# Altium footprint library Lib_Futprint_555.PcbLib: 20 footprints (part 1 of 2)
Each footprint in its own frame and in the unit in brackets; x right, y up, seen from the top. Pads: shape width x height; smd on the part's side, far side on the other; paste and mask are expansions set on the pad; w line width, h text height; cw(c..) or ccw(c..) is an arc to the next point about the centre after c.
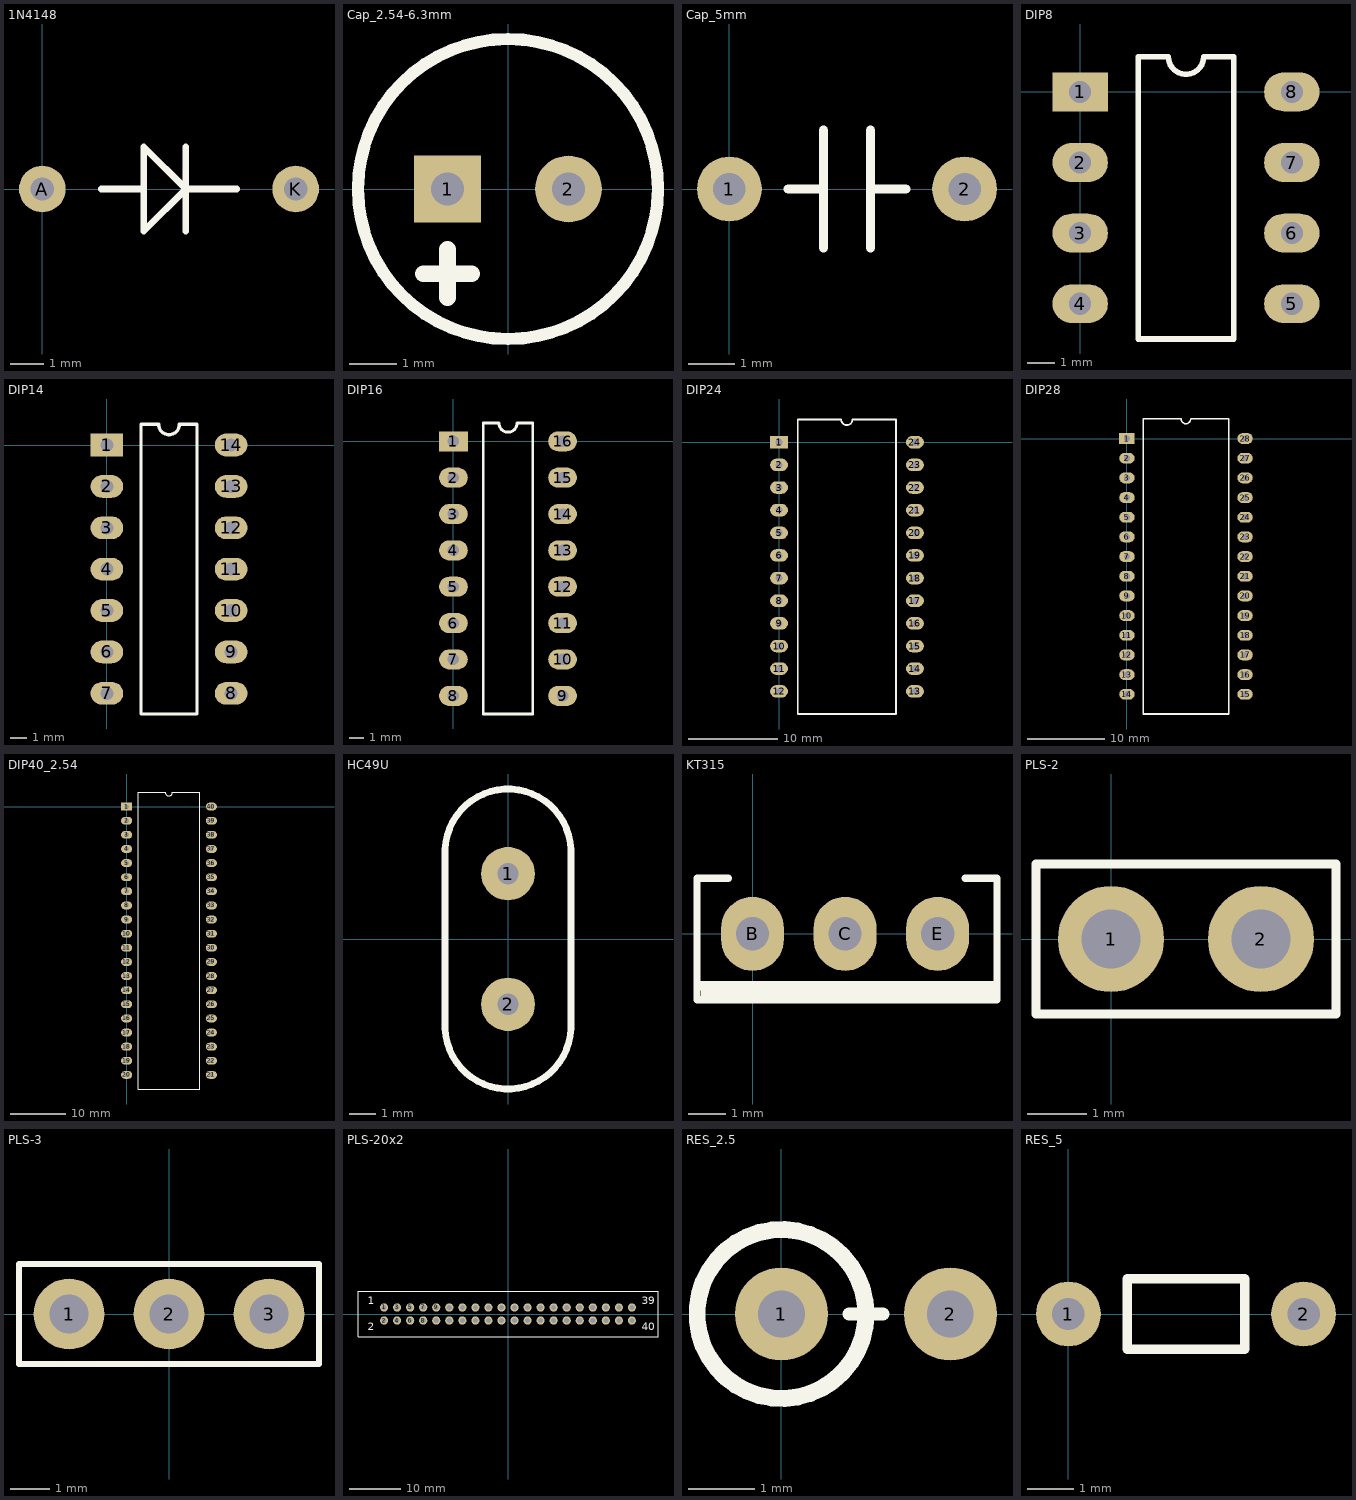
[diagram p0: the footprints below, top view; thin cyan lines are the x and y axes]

## 1N4148 [mm]
pads (2):
  round 1.4 hole 0.7: A(0,0) K(7.62,0)
Top Overlay:
  lines w0.2: 1.778,0 3.048,0 ; 4.318,-1.27 4.318,1.27 ; 5.842,0 4.318,0 ; 4.318,0 3.048,-1.27 3.048,1.27 4.318,0

## Cap_2.54-6.3mm [mm]
pads (2):
  rect 1.4x1.4 hole 0.7: 1(-1.27,0)
  round 1.4 hole 0.7: 2(1.27,0)
Top Overlay:
  circle w0.254: c0,0 r3.15
  lines w0.35: -1.778,-1.778 -0.762,-1.778 ; -1.27,-2.286 -1.27,-1.27
  text ".Designator" at 2.54,5.08 h1.52

## Cap_5mm [mm]
pads (2):
  round 1.4 hole 0.7: 1(0,0) 2(5.08,0)
Top Overlay:
  lines w0.2: 1.27,0 2.032,0 ; 2.032,-1.27 2.032,1.27 ; 3.048,-1.27 3.048,1.27 ; 3.048,0 3.81,0
  text ".Designator" at -0.254,2.032 h1.52

## DIP8 [mm]
pads (8):
  rect 2x1.4 hole 0.8: 1(0,0)
  oval 2x1.4 hole 0.8: 2(0,-2.54) 3(0,-5.08) 4(0,-7.62) 5(7.62,-7.62) 6(7.62,-5.08) 7(7.62,-2.54) 8(7.62,0)
Top Overlay:
  lines w0.2: 2.085,-8.89 5.535,-8.89 5.535,1.27 4.445,1.27 cw(c3.81,1.27) 3.175,1.27 2.085,1.27 2.085,-8.89
  text ".Designator" at 3.175,-0.635 h3.05

## DIP14 [mm]
pads (14):
  rect 2x1.4 hole 0.8: 1(0,0)
  oval 2x1.4 hole 0.8: 2(0,-2.54) 3(0,-5.08) 4(0,-7.62) 5(0,-10.16) 6(0,-12.7) 7(0,-15.24) 8(7.62,-15.24) 9(7.62,-12.7) 10(7.62,-10.16) 11(7.62,-7.62) 12(7.62,-5.08) 13(7.62,-2.54) 14(7.62,0)
Top Overlay:
  lines w0.2: 2.085,-16.51 5.535,-16.51 5.535,1.27 4.445,1.27 cw(c3.81,1.27) 3.175,1.27 2.085,1.27 2.085,-16.51
  text ".Designator" at 3.175,-0.635 h3.05

## DIP16 [mm]
pads (16):
  rect 2x1.4 hole 0.8: 1(0,0)
  oval 2x1.4 hole 0.8: 2(0,-2.54) 3(0,-5.08) 4(0,-7.62) 5(0,-10.16) 6(0,-12.7) 7(0,-15.24) 8(0,-17.78) 9(7.62,-17.78) 10(7.62,-15.24) 11(7.62,-12.7) 12(7.62,-10.16) 13(7.62,-7.62) 14(7.62,-5.08) 15(7.62,-2.54) 16(7.62,0)
Top Overlay:
  lines w0.2: 2.085,-19.05 5.535,-19.05 5.535,1.27 4.445,1.27 cw(c3.81,1.27) 3.175,1.27 2.085,1.27 2.085,-19.05
  text ".Designator" at 3.175,-0.635 h3.05

## DIP24 [mm]
pads (24):
  rect 2x1.4 hole 0.8: 1(0,0)
  oval 2x1.4 hole 0.8: 2(0,-2.54) 3(0,-5.08) 4(0,-7.62) 5(0,-10.16) 6(0,-12.7) 7(0,-15.24) 8(0,-17.78) 9(0,-20.32) 10(0,-22.86) 11(0,-25.4) 12(0,-27.94) 13(15.24,-27.94) 14(15.24,-25.4) 15(15.24,-22.86) 16(15.24,-20.32) 17(15.24,-17.78) 18(15.24,-15.24) 19(15.24,-12.7) 20(15.24,-10.16) 21(15.24,-7.62) 22(15.24,-5.08) 23(15.24,-2.54) 24(15.24,0)
Top Overlay:
  lines w0.2: 6.922,2.54 2.085,2.54 2.085,-30.48 13.115,-30.48 13.115,2.54 8.225,2.54 cw(c7.6,2.54) 6.975,2.54
  text ".Designator" at 1.524,4.318 h1.52

## DIP28 [mm]
pads (28):
  rect 2x1.4 hole 0.8: 1(0,0)
  oval 2x1.4 hole 0.8: 2(0,-2.54) 3(0,-5.08) 4(0,-7.62) 5(0,-10.16) 6(0,-12.7) 7(0,-15.24) 8(0,-17.78) 9(0,-20.32) 10(0,-22.86) 11(0,-25.4) 12(0,-27.94) 13(0,-30.48) 14(0,-33.02) 15(15.24,-33.02) 16(15.24,-30.48) 17(15.24,-27.94) 18(15.24,-25.4) 19(15.24,-22.86) 20(15.24,-20.32) 21(15.24,-17.78) 22(15.24,-15.24) 23(15.24,-12.7) 24(15.24,-10.16) 25(15.24,-7.62) 26(15.24,-5.08) 27(15.24,-2.54) 28(15.24,0)
Top Overlay:
  lines w0.2: 2.085,-35.56 2.085,2.54 6.975,2.54 ccw(c7.6,2.54) 8.225,2.54 13.115,2.54 13.115,-35.56 2.085,-35.56
  text ".Designator" at 1.016,4.064 h1.52

## DIP40_2.54 [mm]
pads (40):
  rect 2x1.4 hole 0.8: 1(0,0)
  oval 2x1.4 hole 0.8: 2(0,-2.54) 3(0,-5.08) 4(0,-7.62) 5(0,-10.16) 6(0,-12.7) 7(0,-15.24) 8(0,-17.78) 9(0,-20.32) 10(0,-22.86) 11(0,-25.4) 12(0,-27.94) 13(0,-30.48) 14(0,-33.02) 15(0,-35.56) 16(0,-38.1) 17(0,-40.64) 18(0,-43.18) 19(0,-45.72) 20(0,-48.26) 21(15.24,-48.26) 22(15.24,-45.72) 23(15.24,-43.18) 24(15.24,-40.64) 25(15.24,-38.1) 26(15.24,-35.56) 27(15.24,-33.02) 28(15.24,-30.48) 29(15.24,-27.94) 30(15.24,-25.4) 31(15.24,-22.86) 32(15.24,-20.32) 33(15.24,-17.78) 34(15.24,-15.24) 35(15.24,-12.7) 36(15.24,-10.16) 37(15.24,-7.62) 38(15.24,-5.08) 39(15.24,-2.54) 40(15.24,0)
Top Overlay:
  lines w0.2: 2.085,-50.8 13.115,-50.8 13.115,2.54 8.225,2.54 cw(c7.6,2.54) 6.975,2.54 2.085,2.54 2.085,-50.8
  text ".Designator" at 2.286,4.572 h1.52

## HC49U [mm]
pads (2):
  round 2 hole 0.8: 1(0,2.44) 2(0,-2.44)
Top Overlay:
  lines w0.254: -2.348,-3.342 ccw(c0,-3.25) 2.348,-3.342 2.348,3.342 ccw(c0,3.25) -2.348,3.342 -2.348,-3.342

## KT315 [mm]
pads (3):
  oval 1.7x2 hole 0.9: B(0,0) C(2.5,0) E(5,0)
Top Overlay:
  rectangle: -1.397,-1.778 6.604,-1.397
  lines w0.2: -0.659,1.5 -1.5,1.5 -1.5,-1.778 2.722,-1.778 3.048,-1.778 6.604,-1.778 6.604,1.5 5.739,1.5
  lines w0.254: -1.397,-1.397 6.477,-1.397
  text ".Designator" at -1.016,2.54 h1.52

## PLS-2 [mm]
pads (2):
  round 1.8 hole 1: 1(0,0) 2(2.54,0)
Top Overlay:
  lines w0.15: -1.27,-1.27 -1.27,1.27 3.81,1.27 3.81,-1.27 -1.27,-1.27

## PLS-3 [mm]
pads (3):
  round 1.8 hole 1: 1(-2.54,0) 2(0,0) 3(2.54,0)
Top Overlay:
  lines w0.15: -3.81,-1.27 -3.81,1.27 3.81,1.27 3.81,-1.27 -3.81,-1.27

## PLS-20x2 [mm]
pads (40):
  round 1.6 hole 1: 1(-24.13,1.27) 2(-24.13,-1.27) 3(-21.59,1.27) 4(-21.59,-1.27) 5(-19.05,1.27) 6(-19.05,-1.27) 7(-16.51,1.27) 8(-16.51,-1.27) 9(-13.97,1.27) 10(-13.97,-1.27) 11(-11.43,1.27) 12(-11.43,-1.27) 13(-8.89,1.27) 14(-8.89,-1.27) 15(-6.35,1.27) 16(-6.35,-1.27) 17(-3.81,1.27) 18(-3.81,-1.27) 19(-1.27,1.27) 20(-1.27,-1.27) 21(1.27,1.27) 22(1.27,-1.27) 23(3.81,1.27) 24(3.81,-1.27) 25(6.35,1.27) 26(6.35,-1.27) 27(8.89,1.27) 28(8.89,-1.27) 29(11.43,1.27) 30(11.43,-1.27) 31(13.97,1.27) 32(13.97,-1.27) 33(16.51,1.27) 34(16.51,-1.27) 35(19.05,1.27) 36(19.05,-1.27) 37(21.59,1.27) 38(21.59,-1.27) 39(24.13,1.27) 40(24.13,-1.27)
Top Overlay:
  lines w0.2: -29.21,-4.445 0,-4.445 29.21,-4.445 29.21,4.445 0,4.445 -29.21,4.445 -29.21,-4.445
  text "40" at 26.035,-3.175 h1.52
  text "39" at 26.035,1.905 h1.52
  text "2" at -27.305,-3.175 h1.52
  text "1" at -27.305,1.905 h1.52

## RES_2.5 [mm]
pads (2):
  round 1.4 hole 0.7: 1(0,0) 2(2.54,0)
Top Overlay:
  circle w0.254: c0,0 r1.27
  lines w0.2: 1.016,0 1.524,0
  text ".Designator" at 2.032,1.524 h1.52

## RES_5 [mm]
pads (2):
  round 1.4 hole 0.7: 1(0,0) 2(5.08,0)
Top Overlay:
  lines w0.2: 1.27,-0.762 1.27,0.762 3.81,0.762 3.81,-0.762 1.27,-0.762
  text ".Designator" at 2.032,1.778 h1.52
